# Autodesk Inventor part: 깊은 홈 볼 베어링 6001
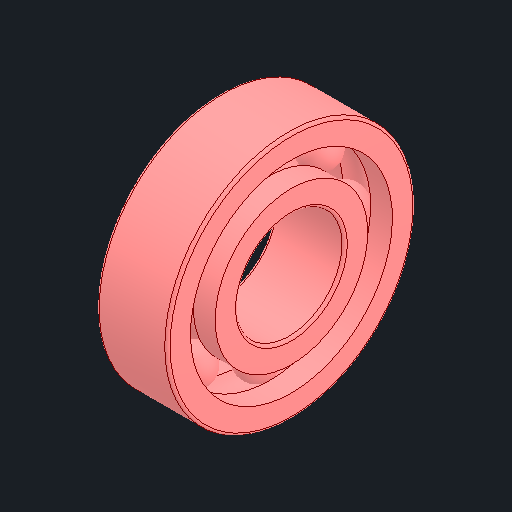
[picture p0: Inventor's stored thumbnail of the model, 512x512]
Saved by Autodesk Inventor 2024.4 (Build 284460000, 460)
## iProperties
Created: 2026-03
Part Number: 깊은 홈 볼 베어링 6001
Material: 강철, 연강
Description: 깊은 그루브 볼 베어링
Document SubType Name: Modeling
Designer: user
Density: 7.85 g/cm^3
Appearance: 기본값
Author: jhkim
Sending System: Autodesk Inventor 2026
Preprocessor: ST-DEVELOPER v20.1
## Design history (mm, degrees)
feature "Solid1"
feature "Solid1:1"
feature "Solid1:2"
feature "Solid1:3"
feature "Solid1:4"
feature "Solid1:5"
feature "Solid1:6"
feature "Solid1:7"
feature "Solid1:8"
feature "Solid1:9"
node "솔리드1"
node "솔리드2"
node "솔리드3"
node "솔리드4"
node "솔리드5"
node "솔리드6"
node "솔리드7"
node "솔리드8"
node "솔리드9"
node "솔리드10"
